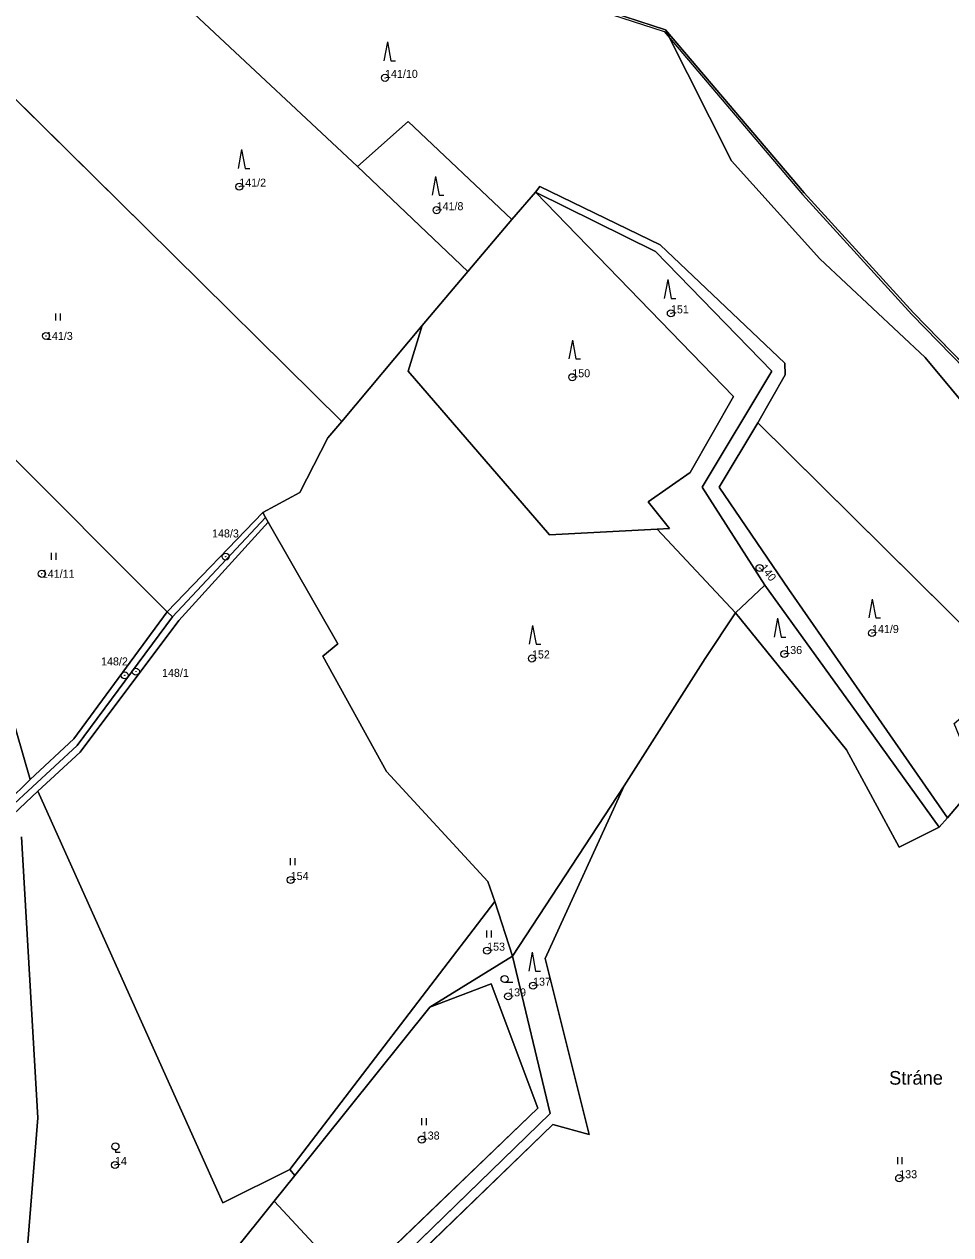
# Model space of a CAD drawing. Extents: x -652854 to -650068, y -1097661 to -1095417.
# Drawn here: x -650819.6 to -650622.9, y -1095838.2 to -1095581.1 of the extents above; entities that cross this region are included whole.
import ezdxf

# ---------------------------------------------------------------- set-up
doc = ezdxf.new("R2010")
doc.units = 0
for name, color, linetype in [('Definiční body parcel', 7, 'Continuous'), ('Hranice obcí', 7, 'Continuous'), ('Hranice parcel', 7, 'Continuous'), ('Názvy', 7, 'Continuous'), ('Obvody jako plochy', 7, 'Continuous'), ('Ostatní hranice', 7, 'Continuous'), ('Parcelní čísla', 7, 'Continuous'), ('Prvky pro prodl_ par_ č_', 7, 'Continuous'), ('Značky kultur', 7, 'Continuous')]:
    doc.layers.add(name, color=color, linetype=linetype)

msp = doc.modelspace()

# ---------------------------------------------------------------- linework, layer by layer
at = {"layer": 'Definiční body parcel'}
for centre, radius in [((-650743, -1095592.54), 0.75), ((-650743, -1095592.54), 0.0327), ((-650773.94, -1095615.64), 0.75), ((-650773.94, -1095615.64), 0.0327), ((-650732.05, -1095620.64), 0.75), ((-650732.05, -1095620.64), 0.0327), ((-650682.31, -1095642.54), 0.75), ((-650682.31, -1095642.54), 0.0327), ((-650814.98, -1095647.34), 0.75), ((-650814.98, -1095647.34), 0.0327), ((-650703.25, -1095656.11), 0.75), ((-650703.25, -1095656.11), 0.0327), ((-650776.83, -1095694.2), 0.75), ((-650776.83, -1095694.2), 0.0327), ((-650815.86, -1095697.85), 0.75), ((-650663.49, -1095696.61), 0.75), ((-650663.49, -1095696.61), 0.0327), ((-650815.86, -1095697.85), 0.0327), ((-650639.63, -1095710.43), 0.75), ((-650639.63, -1095710.43), 0.0327), ((-650711.81, -1095715.83), 0.75), ((-650658.25, -1095714.88), 0.75), ((-650658.25, -1095714.88), 0.0327), ((-650711.81, -1095715.83), 0.0327), ((-650798.27, -1095719.42), 0.75), ((-650798.27, -1095719.42), 0.0327), ((-650795.9, -1095718.63), 0.75), ((-650795.9, -1095718.63), 0.0327), ((-650763.02, -1095762.86), 0.75), ((-650763.02, -1095762.86), 0.0327), ((-650721.32, -1095777.87), 0.75), ((-650721.32, -1095777.87), 0.0327), ((-650711.57, -1095785.31), 0.75), ((-650716.86, -1095787.58), 0.75), ((-650711.57, -1095785.31), 0.0327), ((-650716.86, -1095787.58), 0.0327), ((-650735.2, -1095817.98), 0.75), ((-650735.2, -1095817.98), 0.0327), ((-650800.33, -1095823.39), 0.75), ((-650800.33, -1095823.39), 0.0327), ((-650633.84, -1095826.19), 0.75), ((-650633.84, -1095826.19), 0.0327)]:
    msp.add_circle(centre, radius, dxfattribs=at)
at = {"layer": 'Hranice obcí'}
for p, q in [((-650726.87, -1095568.17), (-650683.44, -1095582.32)), ((-650683.44, -1095582.32), (-650654.04, -1095616.92)), ((-650654.04, -1095616.92), (-650630.81, -1095642.44)), ((-650630.81, -1095642.44), (-650606.83, -1095667.07))]:
    msp.add_line(p, q, dxfattribs=at)
at = {"layer": 'Hranice parcel'}
for p, q in [((-650782.47, -1095579.91), (-650748.84, -1095611.39)), ((-650669.48, -1095610.17), (-650683.44, -1095582.32)), ((-650833.99, -1095584.78), (-650793.83, -1095624.33)), ((-650748.84, -1095611.39), (-650738.08, -1095601.78)), ((-650738.08, -1095601.78), (-650716.05, -1095622.63)), ((-650748.84, -1095611.39), (-650725.42, -1095633.65)), ((-650650.68, -1095630.97), (-650669.48, -1095610.17)), ((-650716.05, -1095622.63), (-650711.08, -1095616.78)), ((-650710.13, -1095615.6), (-650711.08, -1095616.78)), ((-650685.6, -1095629.38), (-650711.08, -1095616.78)), ((-650711.08, -1095616.78), (-650669.05, -1095660.23)), ((-650684.56, -1095627.98), (-650710.13, -1095615.6)), ((-650725.42, -1095633.65), (-650716.05, -1095622.63)), ((-650793.83, -1095624.33), (-650752.15, -1095665.53)), ((-650660.86, -1095654.84), (-650685.6, -1095629.38)), ((-650658.11, -1095653.13), (-650684.56, -1095627.98)), ((-650628.31, -1095651.9), (-650650.68, -1095630.97)), ((-650735.12, -1095645.14), (-650725.42, -1095633.65)), ((-650752.15, -1095665.53), (-650735.12, -1095645.14)), ((-650738.09, -1095654.81), (-650735.12, -1095645.14)), ((-650658.07, -1095655.6), (-650658.11, -1095653.13)), ((-650614.63, -1095668.43), (-650628.31, -1095651.9)), ((-650708.1, -1095689.6), (-650738.09, -1095654.81)), ((-650675.65, -1095679.47), (-650660.86, -1095654.84)), ((-650663.87, -1095665.77), (-650658.07, -1095655.6)), ((-650669.05, -1095660.23), (-650678.21, -1095676.31)), ((-650752.15, -1095665.53), (-650755.12, -1095669)), ((-650663.87, -1095665.77), (-650672.04, -1095679.42)), ((-650609.93, -1095719.17), (-650663.87, -1095665.77)), ((-650755.12, -1095669), (-650761.09, -1095680.61)), ((-650824.98, -1095670.21), (-650789.28, -1095705.95)), ((-650678.21, -1095676.31), (-650687.11, -1095682.58)), ((-650761.09, -1095680.61), (-650768.91, -1095684.86)), ((-650662.4, -1095700.24), (-650675.65, -1095679.47)), ((-650672.04, -1095679.42), (-650657.28, -1095701.2)), ((-650687.11, -1095682.58), (-650682.61, -1095688.23)), ((-650768.91, -1095684.86), (-650789.28, -1095705.95)), ((-650768.34, -1095685.9), (-650788.14, -1095706.99)), ((-650767.79, -1095686.92), (-650786.76, -1095707.77)), ((-650768.91, -1095684.86), (-650768.34, -1095685.9)), ((-650768.34, -1095685.9), (-650767.79, -1095686.92)), ((-650767.79, -1095686.92), (-650753.05, -1095712.71)), ((-650685.24, -1095688.38), (-650708.1, -1095689.6)), ((-650682.61, -1095688.23), (-650685.24, -1095688.38)), ((-650668.63, -1095706.14), (-650685.24, -1095688.38)), ((-650818.36, -1095741.53), (-650832.81, -1095691.31)), ((-650668.63, -1095706.14), (-650662.4, -1095700.24)), ((-650643.85, -1095725.98), (-650662.4, -1095700.24)), ((-650657.28, -1095701.2), (-650641.16, -1095724.38)), ((-650789.28, -1095705.95), (-650809.03, -1095732.92)), ((-650788.14, -1095706.99), (-650808.36, -1095734.29)), ((-650789.28, -1095705.95), (-650788.14, -1095706.99)), ((-650675.04, -1095715.85), (-650668.63, -1095706.14)), ((-650645.07, -1095735.22), (-650668.63, -1095706.14)), ((-650786.76, -1095707.77), (-650807.71, -1095735.72)), ((-650753.05, -1095712.71), (-650756.23, -1095715.33)), ((-650756.23, -1095715.33), (-650742.72, -1095739.81)), ((-650692.25, -1095742.86), (-650675.04, -1095715.85)), ((-650641.16, -1095724.38), (-650623.63, -1095749.68)), ((-650625.37, -1095751.64), (-650643.85, -1095725.98)), ((-650809.03, -1095732.92), (-650818.36, -1095741.53)), ((-650808.36, -1095734.29), (-650822.61, -1095747.49)), ((-650807.71, -1095735.72), (-650816.71, -1095744.03)), ((-650633.88, -1095755.89), (-650645.07, -1095735.22)), ((-650742.72, -1095739.81), (-650721.2, -1095763.18)), ((-650818.36, -1095741.53), (-650823.21, -1095746.31)), ((-650715.92, -1095779.02), (-650692.25, -1095742.86)), ((-650692.25, -1095742.86), (-650709.03, -1095779.57)), ((-650821.9, -1095748.87), (-650816.71, -1095744.03)), ((-650777.42, -1095831.39), (-650816.71, -1095744.03)), ((-650623.63, -1095749.68), (-650619.29, -1095744.55)), ((-650623.63, -1095749.68), (-650625.37, -1095751.64)), ((-650816.69, -1095813.37), (-650820.19, -1095753.68)), ((-650625.37, -1095751.64), (-650633.88, -1095755.89)), ((-650721.2, -1095763.18), (-650719.72, -1095767.45)), ((-650719.72, -1095767.45), (-650763.23, -1095824.34)), ((-650719.72, -1095767.45), (-650715.92, -1095779.02)), ((-650715.92, -1095779.02), (-650733.52, -1095789.9)), ((-650715.92, -1095779.02), (-650707.91, -1095812.42)), ((-650709.03, -1095779.57), (-650699.64, -1095816.89)), ((-650720.49, -1095784.94), (-650733.52, -1095789.9)), ((-650710.55, -1095811.33), (-650720.49, -1095784.94)), ((-650733.52, -1095789.9), (-650762.13, -1095825.6)), ((-650749.82, -1095849.06), (-650710.55, -1095811.33)), ((-650707.91, -1095812.42), (-650740.66, -1095844.24)), ((-650818.83, -1095839.82), (-650816.69, -1095813.37)), ((-650707.4, -1095814.79), (-650739.26, -1095845.66)), ((-650699.64, -1095816.89), (-650707.4, -1095814.79)), ((-650763.23, -1095824.34), (-650777.42, -1095831.39)), ((-650762.13, -1095825.6), (-650766.51, -1095831.07)), ((-650763.23, -1095824.34), (-650762.13, -1095825.6)), ((-650775.65, -1095842.44), (-650766.51, -1095831.07)), ((-650766.51, -1095831.07), (-650749.82, -1095849.06))]:
    msp.add_line(p, q, dxfattribs=at)
at = {"layer": 'Obvody jako plochy'}
for points in [[(-650817.61, -1095546.99), (-650819.64, -1095561.23), (-650820.27, -1095563.98), (-650827.25, -1095576.64), (-650833.99, -1095584.78), (-650793.83, -1095624.33), (-650752.15, -1095665.53), (-650735.12, -1095645.14), (-650725.42, -1095633.65), (-650748.84, -1095611.39), (-650782.47, -1095579.91)], [(-650654.04, -1095616.92), (-650683.44, -1095582.32), (-650669.48, -1095610.17), (-650650.68, -1095630.97), (-650628.31, -1095651.9), (-650614.63, -1095668.43), (-650604.18, -1095679.45), (-650585.5, -1095693.58), (-650578.92, -1095698.55), (-650545.49, -1095728.66), (-650549.8, -1095742.14), (-650553.04, -1095752.26), (-650554.24, -1095756), (-650547.69, -1095768.77), (-650548.93, -1095777.36), (-650514.67, -1095724.6), (-650530.51, -1095718.67), (-650553.83, -1095703.34), (-650583.15, -1095684.58), (-650606.83, -1095667.07), (-650630.81, -1095642.44)], [(-650755.12, -1095669), (-650752.15, -1095665.53), (-650793.83, -1095624.33), (-650833.99, -1095584.78), (-650835.5, -1095586.31), (-650845.17, -1095596.13), (-650853.09, -1095604.56), (-650862.18, -1095622.48), (-650866.94, -1095628.35), (-650824.98, -1095670.21), (-650789.28, -1095705.95), (-650768.91, -1095684.86), (-650761.09, -1095680.61)], [(-650748.84, -1095611.39), (-650725.42, -1095633.65), (-650716.05, -1095622.63), (-650738.08, -1095601.78)], [(-650735.12, -1095645.14), (-650738.09, -1095654.81), (-650708.1, -1095689.6), (-650685.24, -1095688.38), (-650682.61, -1095688.23), (-650687.11, -1095682.58), (-650678.21, -1095676.31), (-650669.05, -1095660.23), (-650711.08, -1095616.78), (-650716.05, -1095622.63), (-650725.42, -1095633.65)], [(-650663.87, -1095665.77), (-650658.07, -1095655.6), (-650658.11, -1095653.13), (-650684.56, -1095627.98), (-650710.13, -1095615.6), (-650711.08, -1095616.78), (-650685.6, -1095629.38), (-650660.86, -1095654.84), (-650675.65, -1095679.47), (-650662.4, -1095700.24), (-650643.85, -1095725.98), (-650625.37, -1095751.64), (-650623.63, -1095749.68), (-650641.16, -1095724.38), (-650657.28, -1095701.2), (-650672.04, -1095679.42)], [(-650668.63, -1095706.14), (-650662.4, -1095700.24), (-650675.65, -1095679.47), (-650660.86, -1095654.84), (-650685.6, -1095629.38), (-650711.08, -1095616.78), (-650669.05, -1095660.23), (-650678.21, -1095676.31), (-650687.11, -1095682.58), (-650682.61, -1095688.23), (-650685.24, -1095688.38)], [(-650853.03, -1095655.29), (-650832.81, -1095691.31), (-650818.36, -1095741.53), (-650809.03, -1095732.92), (-650789.28, -1095705.95), (-650824.98, -1095670.21), (-650866.94, -1095628.35), (-650870.79, -1095632.18)], [(-650755.12, -1095669), (-650761.09, -1095680.61), (-650768.91, -1095684.86), (-650768.34, -1095685.9), (-650767.79, -1095686.92), (-650753.05, -1095712.71), (-650756.23, -1095715.33), (-650742.72, -1095739.81), (-650721.2, -1095763.18), (-650719.72, -1095767.45), (-650715.92, -1095779.02), (-650692.25, -1095742.86), (-650675.04, -1095715.85), (-650668.63, -1095706.14), (-650685.24, -1095688.38), (-650708.1, -1095689.6), (-650738.09, -1095654.81), (-650735.12, -1095645.14), (-650752.15, -1095665.53)], [(-650609.93, -1095719.17), (-650663.87, -1095665.77), (-650672.04, -1095679.42), (-650657.28, -1095701.2), (-650641.16, -1095724.38), (-650623.63, -1095749.68), (-650619.29, -1095744.55), (-650617.13, -1095741.88), (-650622.17, -1095729.62)], [(-650767.79, -1095686.92), (-650768.34, -1095685.9), (-650788.14, -1095706.99), (-650808.36, -1095734.29), (-650822.61, -1095747.49), (-650821.9, -1095748.87), (-650816.71, -1095744.03), (-650807.71, -1095735.72), (-650786.76, -1095707.77)], [(-650721.2, -1095763.18), (-650742.72, -1095739.81), (-650756.23, -1095715.33), (-650753.05, -1095712.71), (-650767.79, -1095686.92), (-650786.76, -1095707.77), (-650807.71, -1095735.72), (-650816.71, -1095744.03), (-650777.42, -1095831.39), (-650763.23, -1095824.34), (-650719.72, -1095767.45)], [(-650768.91, -1095684.86), (-650789.28, -1095705.95), (-650788.14, -1095706.99), (-650768.34, -1095685.9)], [(-650625.37, -1095751.64), (-650643.85, -1095725.98), (-650662.4, -1095700.24), (-650668.63, -1095706.14), (-650645.07, -1095735.22), (-650633.88, -1095755.89)], [(-650823.21, -1095746.31), (-650822.61, -1095747.49), (-650808.36, -1095734.29), (-650788.14, -1095706.99), (-650789.28, -1095705.95), (-650809.03, -1095732.92), (-650818.36, -1095741.53)], [(-650715.92, -1095779.02), (-650707.91, -1095812.42), (-650740.66, -1095844.24), (-650742.53, -1095850.77), (-650739.26, -1095845.66), (-650707.4, -1095814.79), (-650699.64, -1095816.89), (-650709.03, -1095779.57), (-650692.25, -1095742.86)], [(-650719.72, -1095767.45), (-650763.23, -1095824.34), (-650762.13, -1095825.6), (-650733.52, -1095789.9), (-650715.92, -1095779.02)], [(-650715.92, -1095779.02), (-650733.52, -1095789.9), (-650720.49, -1095784.94), (-650710.55, -1095811.33), (-650749.82, -1095849.06), (-650742.53, -1095850.77), (-650740.66, -1095844.24), (-650707.91, -1095812.42)], [(-650749.82, -1095849.06), (-650710.55, -1095811.33), (-650720.49, -1095784.94), (-650733.52, -1095789.9), (-650762.13, -1095825.6), (-650766.51, -1095831.07)], [(-650742.53, -1095850.77), (-650749.82, -1095849.06), (-650766.51, -1095831.07), (-650775.65, -1095842.44), (-650767.52, -1095859.75), (-650796.27, -1095886.77), (-650783.98, -1095898.17), (-650770.5, -1095885.45), (-650763.57, -1095878.9), (-650753.65, -1095888.94), (-650745.45, -1095878.26), (-650741.85, -1095865.29)]]:
    msp.add_lwpolyline(points, close=True, dxfattribs=at)
for points in [[(-650782.47, -1095579.91), (-650748.84, -1095611.39), (-650738.08, -1095601.78), (-650716.05, -1095622.63), (-650711.08, -1095616.78), (-650710.13, -1095615.6), (-650684.56, -1095627.98), (-650658.11, -1095653.13), (-650658.07, -1095655.6), (-650663.87, -1095665.77), (-650609.93, -1095719.17), (-650593.98, -1095732.55), (-650590.54, -1095716.72), (-650585.5, -1095693.58), (-650604.18, -1095679.45), (-650614.63, -1095668.43), (-650628.31, -1095651.9), (-650650.68, -1095630.97), (-650669.48, -1095610.17), (-650683.44, -1095582.32), (-650726.87, -1095568.17)], [(-650823.21, -1095746.31), (-650818.36, -1095741.53), (-650832.81, -1095691.31)], [(-650505.7, -1095846.33), (-650504.91, -1095834.49), (-650495.09, -1095809.68), (-650508.67, -1095805.16), (-650538.3, -1095802.8), (-650546.41, -1095786.02), (-650591.47, -1095769.26), (-650619.29, -1095744.55), (-650623.63, -1095749.68), (-650625.37, -1095751.64), (-650633.88, -1095755.89), (-650645.07, -1095735.22), (-650668.63, -1095706.14), (-650675.04, -1095715.85), (-650692.25, -1095742.86), (-650709.03, -1095779.57), (-650699.64, -1095816.89), (-650707.4, -1095814.79), (-650739.26, -1095845.66)], [(-650775.65, -1095842.44), (-650766.51, -1095831.07), (-650762.13, -1095825.6), (-650763.23, -1095824.34), (-650777.42, -1095831.39), (-650816.71, -1095744.03), (-650821.9, -1095748.87)], [(-650840.77, -1095939.29), (-650817.24, -1095917.02), (-650804.63, -1095908.11), (-650797.09, -1095902.55), (-650790.39, -1095897.52), (-650796.27, -1095886.77), (-650799.6, -1095882.56), (-650813.36, -1095863.05), (-650815.85, -1095857.15), (-650818.41, -1095847.67), (-650818.59, -1095844.63), (-650818.83, -1095839.82), (-650816.69, -1095813.37), (-650820.19, -1095753.68)], [(-650820.19, -1095753.68), (-650816.69, -1095813.37), (-650818.83, -1095839.82)]]:
    msp.add_lwpolyline(points, dxfattribs=at)
at = {"layer": 'Ostatní hranice'}
for p, q in [((-650727.11, -1095568.59), (-650683.74, -1095582.71)), ((-650683.74, -1095582.71), (-650654.4, -1095617.28)), ((-650654.4, -1095617.28), (-650631.17, -1095642.8)), ((-650631.17, -1095642.8), (-650607.14, -1095667.48))]:
    msp.add_line(p, q, dxfattribs=at)
at = {"layer": 'Značky kultur'}
for p, q in [((-650742.492, -1095584.889), (-650743.225, -1095588.889)), ((-650742.492, -1095584.889), (-650741.759, -1095588.889)), ((-650741.759, -1095588.889), (-650740.759, -1095588.889)), ((-650773.442, -1095607.759), (-650774.175, -1095611.759)), ((-650773.442, -1095607.759), (-650772.709, -1095611.759)), ((-650772.709, -1095611.759), (-650771.709, -1095611.759)), ((-650732.262, -1095613.459), (-650732.995, -1095617.459)), ((-650732.262, -1095613.459), (-650731.529, -1095617.459)), ((-650731.529, -1095617.459), (-650730.529, -1095617.459)), ((-650682.992, -1095635.369), (-650683.725, -1095639.369)), ((-650682.992, -1095635.369), (-650682.259, -1095639.369)), ((-650682.259, -1095639.369), (-650681.259, -1095639.369)), ((-650812.937, -1095642.585), (-650812.937, -1095644.085)), ((-650811.915, -1095644.085), (-650811.915, -1095642.585)), ((-650703.222, -1095648.219), (-650703.955, -1095652.219)), ((-650703.222, -1095648.219), (-650702.489, -1095652.219)), ((-650702.489, -1095652.219), (-650701.489, -1095652.219)), ((-650813.867, -1095693.415), (-650813.867, -1095694.915)), ((-650812.845, -1095694.915), (-650812.845, -1095693.415)), ((-650639.562, -1095703.219), (-650640.295, -1095707.219)), ((-650639.562, -1095703.219), (-650638.829, -1095707.219)), ((-650659.672, -1095707.269), (-650660.405, -1095711.269)), ((-650659.672, -1095707.269), (-650658.939, -1095711.269)), ((-650638.829, -1095707.219), (-650637.829, -1095707.219)), ((-650711.672, -1095708.809), (-650712.405, -1095712.809)), ((-650711.672, -1095708.809), (-650710.939, -1095712.809)), ((-650658.939, -1095711.269), (-650657.939, -1095711.269)), ((-650710.939, -1095712.809), (-650709.939, -1095712.809)), ((-650763.117, -1095758.205), (-650763.117, -1095759.705)), ((-650762.095, -1095759.705), (-650762.095, -1095758.205)), ((-650721.427, -1095773.575), (-650721.427, -1095775.075)), ((-650720.405, -1095775.075), (-650720.405, -1095773.575)), ((-650711.762, -1095778.199), (-650712.495, -1095782.199)), ((-650711.762, -1095778.199), (-650711.029, -1095782.199)), ((-650715.88, -1095784.65), (-650717.63, -1095784.65)), ((-650711.029, -1095782.199), (-650710.029, -1095782.199)), ((-650735.247, -1095813.445), (-650735.247, -1095814.945)), ((-650734.225, -1095814.945), (-650734.225, -1095813.445)), ((-650800.23, -1095820.19), (-650800.23, -1095820.69)), ((-650800.23, -1095820.69), (-650799.207, -1095820.69)), ((-650634.237, -1095821.695), (-650634.237, -1095823.195)), ((-650633.215, -1095823.195), (-650633.215, -1095821.695))]:
    msp.add_line(p, q, dxfattribs=at)
for centre in [(-650717.63, -1095783.9), (-650800.23, -1095819.44)]:
    msp.add_circle(centre, 0.75, dxfattribs=at)

# ---------------------------------------------------------------- texts
at = {"layer": 'Názvy'}
msp.add_text('Stráne', height=2.9, dxfattribs=at).set_placement((-650635.99, -1095806.33))
at = {"layer": 'Parcelní čísla'}
for s, p in [('141/10', (-650743, -1095592.54)), ('141/2', (-650773.94, -1095615.64)), ('141/8', (-650732.05, -1095620.64)), ('151', (-650682.31, -1095642.54)), ('141/3', (-650814.98, -1095648.19)), ('150', (-650703.25, -1095656.11)), ('141/11', (-650815.86, -1095698.7)), ('141/9', (-650639.63, -1095710.43)), ('152', (-650711.81, -1095715.83)), ('136', (-650658.25, -1095714.88)), ('154', (-650763.02, -1095762.86)), ('153', (-650721.32, -1095777.87)), ('137', (-650711.57, -1095785.31)), ('139', (-650716.86, -1095787.58)), ('138', (-650735.2, -1095817.98)), ('14', (-650800.33, -1095823.39)), ('133', (-650633.84, -1095826.19))]:
    msp.add_text(s, height=1.7, dxfattribs=at).set_placement(p)
for s, height, rotation, p in [('148/3', 0.1, 46.935, (-650776.793, -1095694.234)), ('140', 1.7, 307.854, (-650663.49, -1095696.61)), ('148/2', 0.1, 51.822, (-650798.231, -1095719.451)), ('148/1', 0.1, 51.462, (-650795.861, -1095718.661))]:
    msp.add_text(s, height=height, rotation=rotation, dxfattribs=at).set_placement(p)
at = {"layer": 'Prvky pro prodl_ par_ č_'}
for s, p in [('148/3', (-650779.72, -1095690.13)), ('148/2', (-650803.28, -1095717.3)), ('148/1', (-650790.34, -1095719.73))]:
    msp.add_text(s, height=1.7, dxfattribs=at).set_placement(p)

doc.saveas('drawing.dxf')
